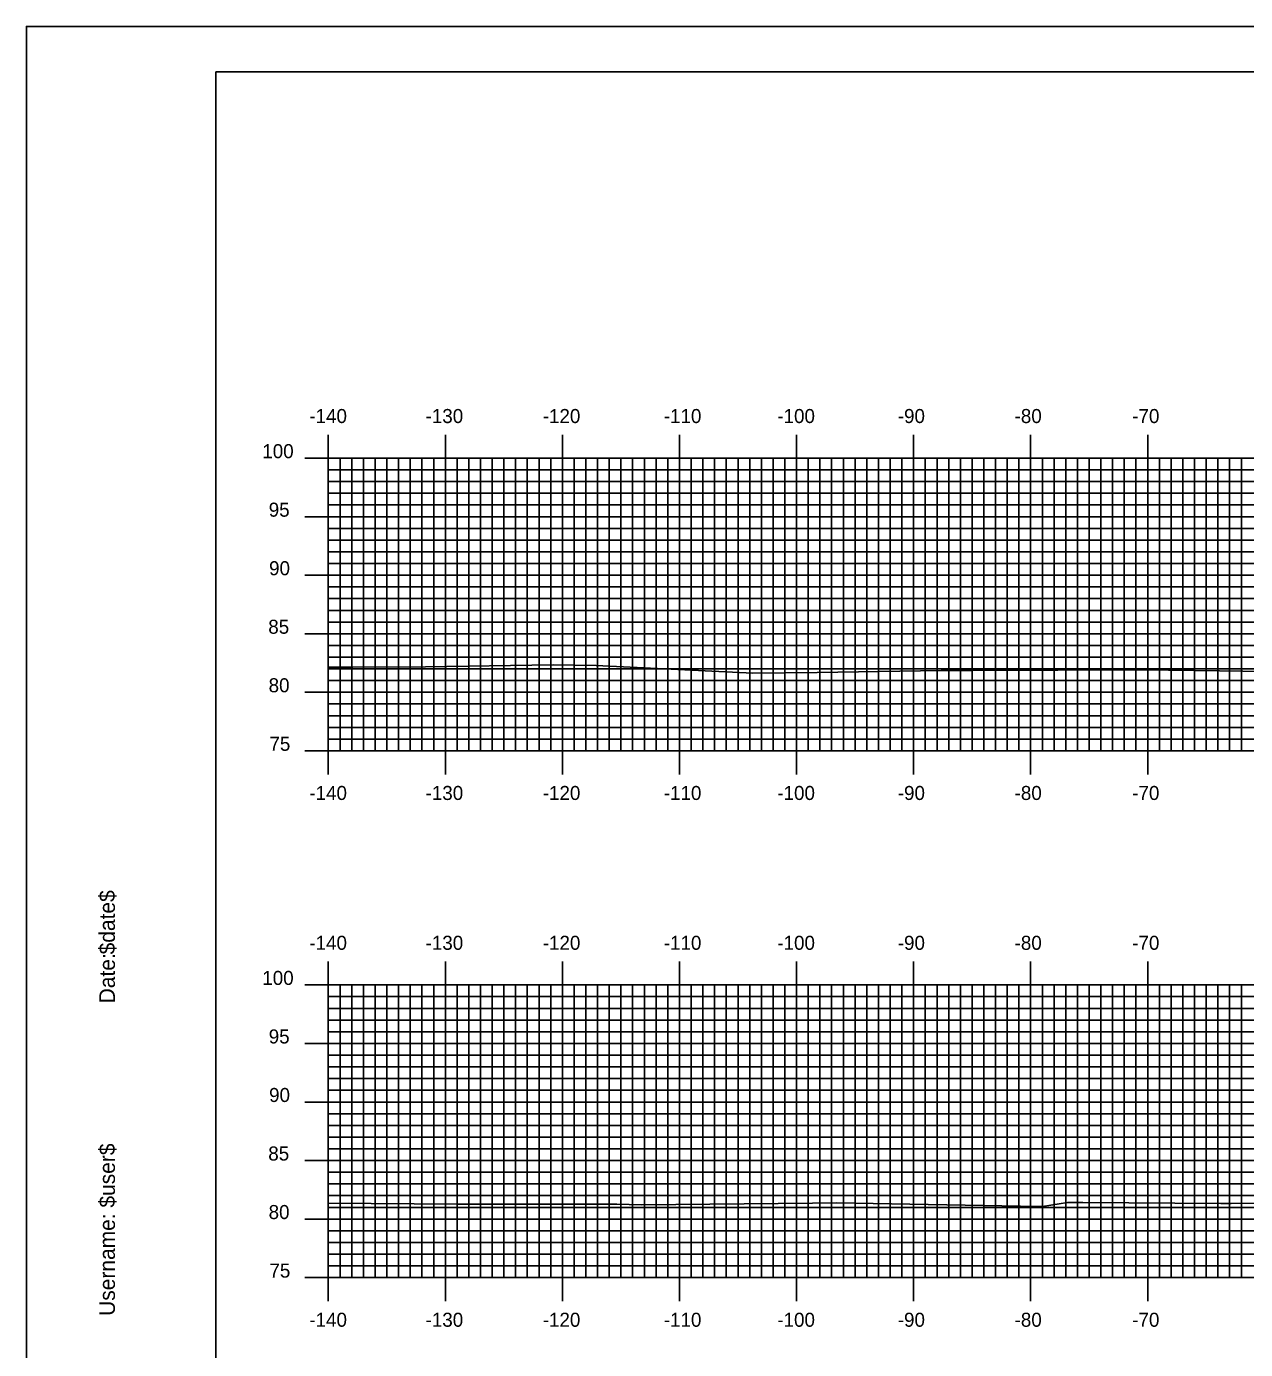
# Model space of a CAD drawing. Extents: x 853723 to 854066, y 364366 to 364586.
# Drawn here: x 853722.9 to 853827.1, y 364472.6 to 364585.7 of the extents above; entities that cross this region are included whole.
import ezdxf

# ---------------------------------------------------------------- set-up
doc = ezdxf.new("R2010")
doc.units = 0
for name, color, linetype in [('BORDER', 7, 'Continuous'), ('H_V ANNOTATION', 7, 'Continuous'), ('MAJOR', 7, 'Continuous'), ('MINOR', 7, 'Continuous'), ('PLOT BOUNDARY', 7, 'Continuous'), ('S_Roadway_Centerline', 7, 'Continuous')]:
    doc.layers.add(name, color=color, linetype=linetype)

msp = doc.modelspace()

# ---------------------------------------------------------------- linework, layer by layer
at = {"layer": 'BORDER'}
msp.add_lwpolyline([(853739.12, 364371.79), (854059.12, 364371.79), (854059.12, 364581.79), (853739.12, 364581.79)], close=True, dxfattribs=at)
at = {"layer": 'MAJOR'}
for p, q in [((853748.72, 364550.79), (853748.72, 364548.79)), ((853758.72, 364550.79), (853758.72, 364548.79)), ((853768.72, 364550.79), (853768.72, 364548.79)), ((853778.72, 364550.79), (853778.72, 364548.79)), ((853788.72, 364550.79), (853788.72, 364548.79)), ((853798.72, 364550.79), (853798.72, 364548.79)), ((853808.72, 364550.79), (853808.72, 364548.79)), ((853818.72, 364550.79), (853818.72, 364548.79)), ((853746.71, 364548.79), (853748.72, 364548.79)), ((853748.72, 364548.79), (854028.72, 364548.79)), ((853748.72, 364523.79), (853748.72, 364548.79)), ((853748.72, 364523.79), (853748.72, 364548.79)), ((853748.72, 364548.79), (854028.72, 364548.79)), ((853758.72, 364523.79), (853758.72, 364548.79)), ((853768.72, 364523.79), (853768.72, 364548.79)), ((853778.72, 364523.79), (853778.72, 364548.79)), ((853788.72, 364523.79), (853788.72, 364548.79)), ((853798.72, 364523.79), (853798.72, 364548.79)), ((853808.72, 364523.79), (853808.72, 364548.79)), ((853818.72, 364523.79), (853818.72, 364548.79)), ((853746.71, 364543.79), (853748.72, 364543.79)), ((853748.72, 364543.79), (854028.72, 364543.79)), ((853746.71, 364538.79), (853748.72, 364538.79)), ((853748.72, 364538.79), (854028.72, 364538.79)), ((853746.71, 364533.79), (853748.72, 364533.79)), ((853748.72, 364533.79), (854028.72, 364533.79)), ((853746.71, 364528.79), (853748.72, 364528.79)), ((853748.72, 364528.79), (854028.72, 364528.79)), ((853746.71, 364523.79), (853748.72, 364523.79)), ((853748.72, 364523.79), (854028.72, 364523.79)), ((853748.72, 364523.79), (854028.72, 364523.79)), ((853748.72, 364521.78), (853748.72, 364523.79)), ((853758.72, 364521.78), (853758.72, 364523.79)), ((853768.72, 364521.78), (853768.72, 364523.79)), ((853778.72, 364521.78), (853778.72, 364523.79)), ((853788.72, 364521.78), (853788.72, 364523.79)), ((853798.72, 364521.78), (853798.72, 364523.79)), ((853808.72, 364521.78), (853808.72, 364523.79)), ((853818.72, 364521.78), (853818.72, 364523.79)), ((853748.72, 364505.79), (853748.72, 364503.79)), ((853758.72, 364505.79), (853758.72, 364503.79)), ((853768.72, 364505.79), (853768.72, 364503.79)), ((853778.72, 364505.79), (853778.72, 364503.79)), ((853788.72, 364505.79), (853788.72, 364503.79)), ((853798.72, 364505.79), (853798.72, 364503.79)), ((853808.72, 364505.79), (853808.72, 364503.79)), ((853818.72, 364505.79), (853818.72, 364503.79)), ((853746.71, 364503.79), (853748.72, 364503.79)), ((853748.72, 364503.79), (854028.72, 364503.79)), ((853748.72, 364478.79), (853748.72, 364503.79)), ((853748.72, 364478.79), (853748.72, 364503.79)), ((853748.72, 364503.79), (854028.72, 364503.79)), ((853758.72, 364478.79), (853758.72, 364503.79)), ((853768.72, 364478.79), (853768.72, 364503.79)), ((853778.72, 364478.79), (853778.72, 364503.79)), ((853788.72, 364478.79), (853788.72, 364503.79)), ((853798.72, 364478.79), (853798.72, 364503.79)), ((853808.72, 364478.79), (853808.72, 364503.79)), ((853818.72, 364478.79), (853818.72, 364503.79)), ((853746.71, 364498.79), (853748.72, 364498.79)), ((853748.72, 364498.79), (854028.72, 364498.79)), ((853746.71, 364493.79), (853748.72, 364493.79)), ((853748.72, 364493.79), (854028.72, 364493.79)), ((853746.71, 364488.79), (853748.72, 364488.79)), ((853748.72, 364488.79), (854028.72, 364488.79)), ((853746.71, 364483.79), (853748.72, 364483.79)), ((853748.72, 364483.79), (854028.72, 364483.79)), ((853746.71, 364478.79), (853748.72, 364478.79)), ((853748.72, 364478.79), (854028.72, 364478.79)), ((853748.72, 364478.79), (854028.72, 364478.79)), ((853748.72, 364476.78), (853748.72, 364478.79)), ((853758.72, 364476.78), (853758.72, 364478.79)), ((853768.72, 364476.78), (853768.72, 364478.79)), ((853778.72, 364476.78), (853778.72, 364478.79)), ((853788.72, 364476.78), (853788.72, 364478.79)), ((853798.72, 364476.78), (853798.72, 364478.79)), ((853808.72, 364476.78), (853808.72, 364478.79)), ((853818.72, 364476.78), (853818.72, 364478.79))]:
    msp.add_line(p, q, dxfattribs=at)
at = {"layer": 'MINOR'}
for p, q in [((853749.72, 364523.79), (853749.72, 364548.79)), ((853750.72, 364523.79), (853750.72, 364548.79)), ((853751.72, 364523.79), (853751.72, 364548.79)), ((853752.72, 364523.79), (853752.72, 364548.79)), ((853753.72, 364523.79), (853753.72, 364548.79)), ((853754.72, 364523.79), (853754.72, 364548.79)), ((853755.72, 364523.79), (853755.72, 364548.79)), ((853756.72, 364523.79), (853756.72, 364548.79)), ((853757.72, 364523.79), (853757.72, 364548.79)), ((853759.72, 364523.79), (853759.72, 364548.79)), ((853760.72, 364523.79), (853760.72, 364548.79)), ((853761.72, 364523.79), (853761.72, 364548.79)), ((853762.72, 364523.79), (853762.72, 364548.79)), ((853763.72, 364523.79), (853763.72, 364548.79)), ((853764.72, 364523.79), (853764.72, 364548.79)), ((853765.72, 364523.79), (853765.72, 364548.79)), ((853766.72, 364523.79), (853766.72, 364548.79)), ((853767.72, 364523.79), (853767.72, 364548.79)), ((853769.72, 364523.79), (853769.72, 364548.79)), ((853770.72, 364523.79), (853770.72, 364548.79)), ((853771.72, 364523.79), (853771.72, 364548.79)), ((853772.72, 364523.79), (853772.72, 364548.79)), ((853773.72, 364523.79), (853773.72, 364548.79)), ((853774.72, 364523.79), (853774.72, 364548.79)), ((853775.72, 364523.79), (853775.72, 364548.79)), ((853776.72, 364523.79), (853776.72, 364548.79)), ((853777.72, 364523.79), (853777.72, 364548.79)), ((853779.72, 364523.79), (853779.72, 364548.79)), ((853780.72, 364523.79), (853780.72, 364548.79)), ((853781.72, 364523.79), (853781.72, 364548.79)), ((853782.72, 364523.79), (853782.72, 364548.79)), ((853783.72, 364523.79), (853783.72, 364548.79)), ((853784.72, 364523.79), (853784.72, 364548.79)), ((853785.72, 364523.79), (853785.72, 364548.79)), ((853786.72, 364523.79), (853786.72, 364548.79)), ((853787.72, 364523.79), (853787.72, 364548.79)), ((853789.72, 364523.79), (853789.72, 364548.79)), ((853790.72, 364523.79), (853790.72, 364548.79)), ((853791.72, 364523.79), (853791.72, 364548.79)), ((853792.72, 364523.79), (853792.72, 364548.79)), ((853793.72, 364523.79), (853793.72, 364548.79)), ((853794.72, 364523.79), (853794.72, 364548.79)), ((853795.72, 364523.79), (853795.72, 364548.79)), ((853796.72, 364523.79), (853796.72, 364548.79)), ((853797.72, 364523.79), (853797.72, 364548.79)), ((853799.72, 364523.79), (853799.72, 364548.79)), ((853800.72, 364523.79), (853800.72, 364548.79)), ((853801.72, 364523.79), (853801.72, 364548.79)), ((853802.72, 364523.79), (853802.72, 364548.79)), ((853803.72, 364523.79), (853803.72, 364548.79)), ((853804.72, 364523.79), (853804.72, 364548.79)), ((853805.72, 364523.79), (853805.72, 364548.79)), ((853806.72, 364523.79), (853806.72, 364548.79)), ((853807.72, 364523.79), (853807.72, 364548.79)), ((853809.72, 364523.79), (853809.72, 364548.79)), ((853810.72, 364523.79), (853810.72, 364548.79)), ((853811.72, 364523.79), (853811.72, 364548.79)), ((853812.72, 364523.79), (853812.72, 364548.79)), ((853813.72, 364523.79), (853813.72, 364548.79)), ((853814.72, 364523.79), (853814.72, 364548.79)), ((853815.72, 364523.79), (853815.72, 364548.79)), ((853816.72, 364523.79), (853816.72, 364548.79)), ((853817.72, 364523.79), (853817.72, 364548.79)), ((853819.72, 364523.79), (853819.72, 364548.79)), ((853820.72, 364523.79), (853820.72, 364548.79)), ((853821.72, 364523.79), (853821.72, 364548.79)), ((853822.72, 364523.79), (853822.72, 364548.79)), ((853823.72, 364523.79), (853823.72, 364548.79)), ((853824.72, 364523.79), (853824.72, 364548.79)), ((853825.72, 364523.79), (853825.72, 364548.79)), ((853826.72, 364523.79), (853826.72, 364548.79)), ((853748.72, 364547.79), (854028.72, 364547.79)), ((853748.72, 364547.79), (853750.72, 364547.79)), ((853748.72, 364546.79), (854028.72, 364546.79)), ((853748.72, 364546.79), (853750.72, 364546.79)), ((853748.72, 364545.79), (854028.72, 364545.79)), ((853748.72, 364545.79), (853750.72, 364545.79)), ((853748.72, 364544.79), (854028.72, 364544.79)), ((853748.72, 364544.79), (853750.72, 364544.79)), ((853748.72, 364542.79), (854028.72, 364542.79)), ((853748.72, 364542.79), (853750.72, 364542.79)), ((853748.72, 364541.79), (854028.72, 364541.79)), ((853748.72, 364541.79), (853750.72, 364541.79)), ((853748.72, 364540.79), (854028.72, 364540.79)), ((853748.72, 364540.79), (853750.72, 364540.79)), ((853748.72, 364539.79), (854028.72, 364539.79)), ((853748.72, 364539.79), (853750.72, 364539.79)), ((853748.72, 364537.79), (854028.72, 364537.79)), ((853748.72, 364537.79), (853750.72, 364537.79)), ((853748.72, 364536.79), (854028.72, 364536.79)), ((853748.72, 364536.79), (853750.72, 364536.79)), ((853748.72, 364535.79), (854028.72, 364535.79)), ((853748.72, 364535.79), (853750.72, 364535.79)), ((853748.72, 364534.79), (854028.72, 364534.79)), ((853748.72, 364534.79), (853750.72, 364534.79)), ((853748.72, 364532.79), (854028.72, 364532.79)), ((853748.72, 364532.79), (853750.72, 364532.79)), ((853748.72, 364531.79), (854028.72, 364531.79)), ((853748.72, 364531.79), (853750.72, 364531.79)), ((853748.72, 364530.79), (854028.72, 364530.79)), ((853748.72, 364530.79), (853750.72, 364530.79)), ((853748.72, 364529.79), (854028.72, 364529.79)), ((853748.72, 364529.79), (853750.72, 364529.79)), ((853748.72, 364527.79), (854028.72, 364527.79)), ((853748.72, 364527.79), (853750.72, 364527.79)), ((853748.72, 364526.79), (854028.72, 364526.79)), ((853748.72, 364526.79), (853750.72, 364526.79)), ((853748.72, 364525.79), (854028.72, 364525.79)), ((853748.72, 364525.79), (853750.72, 364525.79)), ((853748.72, 364524.79), (854028.72, 364524.79)), ((853748.72, 364524.79), (853750.72, 364524.79)), ((853749.72, 364478.79), (853749.72, 364503.79)), ((853750.72, 364478.79), (853750.72, 364503.79)), ((853751.72, 364478.79), (853751.72, 364503.79)), ((853752.72, 364478.79), (853752.72, 364503.79)), ((853753.72, 364478.79), (853753.72, 364503.79)), ((853754.72, 364478.79), (853754.72, 364503.79)), ((853755.72, 364478.79), (853755.72, 364503.79)), ((853756.72, 364478.79), (853756.72, 364503.79)), ((853757.72, 364478.79), (853757.72, 364503.79)), ((853759.72, 364478.79), (853759.72, 364503.79)), ((853760.72, 364478.79), (853760.72, 364503.79)), ((853761.72, 364478.79), (853761.72, 364503.79)), ((853762.72, 364478.79), (853762.72, 364503.79)), ((853763.72, 364478.79), (853763.72, 364503.79)), ((853764.72, 364478.79), (853764.72, 364503.79)), ((853765.72, 364478.79), (853765.72, 364503.79)), ((853766.72, 364478.79), (853766.72, 364503.79)), ((853767.72, 364478.79), (853767.72, 364503.79)), ((853769.72, 364478.79), (853769.72, 364503.79)), ((853770.72, 364478.79), (853770.72, 364503.79)), ((853771.72, 364478.79), (853771.72, 364503.79)), ((853772.72, 364478.79), (853772.72, 364503.79)), ((853773.72, 364478.79), (853773.72, 364503.79)), ((853774.72, 364478.79), (853774.72, 364503.79)), ((853775.72, 364478.79), (853775.72, 364503.79)), ((853776.72, 364478.79), (853776.72, 364503.79)), ((853777.72, 364478.79), (853777.72, 364503.79)), ((853779.72, 364478.79), (853779.72, 364503.79)), ((853780.72, 364478.79), (853780.72, 364503.79)), ((853781.72, 364478.79), (853781.72, 364503.79)), ((853782.72, 364478.79), (853782.72, 364503.79)), ((853783.72, 364478.79), (853783.72, 364503.79)), ((853784.72, 364478.79), (853784.72, 364503.79)), ((853785.72, 364478.79), (853785.72, 364503.79)), ((853786.72, 364478.79), (853786.72, 364503.79)), ((853787.72, 364478.79), (853787.72, 364503.79)), ((853789.72, 364478.79), (853789.72, 364503.79)), ((853790.72, 364478.79), (853790.72, 364503.79)), ((853791.72, 364478.79), (853791.72, 364503.79)), ((853792.72, 364478.79), (853792.72, 364503.79)), ((853793.72, 364478.79), (853793.72, 364503.79)), ((853794.72, 364478.79), (853794.72, 364503.79)), ((853795.72, 364478.79), (853795.72, 364503.79)), ((853796.72, 364478.79), (853796.72, 364503.79)), ((853797.72, 364478.79), (853797.72, 364503.79)), ((853799.72, 364478.79), (853799.72, 364503.79)), ((853800.72, 364478.79), (853800.72, 364503.79)), ((853801.72, 364478.79), (853801.72, 364503.79)), ((853802.72, 364478.79), (853802.72, 364503.79)), ((853803.72, 364478.79), (853803.72, 364503.79)), ((853804.72, 364478.79), (853804.72, 364503.79)), ((853805.72, 364478.79), (853805.72, 364503.79)), ((853806.72, 364478.79), (853806.72, 364503.79)), ((853807.72, 364478.79), (853807.72, 364503.79)), ((853809.72, 364478.79), (853809.72, 364503.79)), ((853810.72, 364478.79), (853810.72, 364503.79)), ((853811.72, 364478.79), (853811.72, 364503.79)), ((853812.72, 364478.79), (853812.72, 364503.79)), ((853813.72, 364478.79), (853813.72, 364503.79)), ((853814.72, 364478.79), (853814.72, 364503.79)), ((853815.72, 364478.79), (853815.72, 364503.79)), ((853816.72, 364478.79), (853816.72, 364503.79)), ((853817.72, 364478.79), (853817.72, 364503.79)), ((853819.72, 364478.79), (853819.72, 364503.79)), ((853820.72, 364478.79), (853820.72, 364503.79)), ((853821.72, 364478.79), (853821.72, 364503.79)), ((853822.72, 364478.79), (853822.72, 364503.79)), ((853823.72, 364478.79), (853823.72, 364503.79)), ((853824.72, 364478.79), (853824.72, 364503.79)), ((853825.72, 364478.79), (853825.72, 364503.79)), ((853826.72, 364478.79), (853826.72, 364503.79)), ((853748.72, 364502.79), (854028.72, 364502.79)), ((853748.72, 364502.79), (853750.72, 364502.79)), ((853748.72, 364501.79), (854028.72, 364501.79)), ((853748.72, 364501.79), (853750.72, 364501.79)), ((853748.72, 364500.79), (854028.72, 364500.79)), ((853748.72, 364500.79), (853750.72, 364500.79)), ((853748.72, 364499.79), (854028.72, 364499.79)), ((853748.72, 364499.79), (853750.72, 364499.79)), ((853748.72, 364497.79), (854028.72, 364497.79)), ((853748.72, 364497.79), (853750.72, 364497.79)), ((853748.72, 364496.79), (854028.72, 364496.79)), ((853748.72, 364496.79), (853750.72, 364496.79)), ((853748.72, 364495.79), (854028.72, 364495.79)), ((853748.72, 364495.79), (853750.72, 364495.79)), ((853748.72, 364494.79), (854028.72, 364494.79)), ((853748.72, 364494.79), (853750.72, 364494.79)), ((853748.72, 364492.79), (854028.72, 364492.79)), ((853748.72, 364492.79), (853750.72, 364492.79)), ((853748.72, 364491.79), (854028.72, 364491.79)), ((853748.72, 364491.79), (853750.72, 364491.79)), ((853748.72, 364490.79), (854028.72, 364490.79)), ((853748.72, 364490.79), (853750.72, 364490.79)), ((853748.72, 364489.79), (854028.72, 364489.79)), ((853748.72, 364489.79), (853750.72, 364489.79)), ((853748.72, 364487.79), (854028.72, 364487.79)), ((853748.72, 364487.79), (853750.72, 364487.79)), ((853748.72, 364486.79), (854028.72, 364486.79)), ((853748.72, 364486.79), (853750.72, 364486.79)), ((853748.72, 364485.79), (854028.72, 364485.79)), ((853748.72, 364485.79), (853750.72, 364485.79)), ((853748.72, 364484.79), (854028.72, 364484.79)), ((853748.72, 364484.79), (853750.72, 364484.79)), ((853748.72, 364482.79), (854028.72, 364482.79)), ((853748.72, 364482.79), (853750.72, 364482.79)), ((853748.72, 364481.79), (854028.72, 364481.79)), ((853748.72, 364481.79), (853750.72, 364481.79)), ((853748.72, 364480.79), (854028.72, 364480.79)), ((853748.72, 364480.79), (853750.72, 364480.79)), ((853748.72, 364479.79), (854028.72, 364479.79)), ((853748.72, 364479.79), (853750.72, 364479.79))]:
    msp.add_line(p, q, dxfattribs=at)
at = {"layer": 'PLOT BOUNDARY'}
msp.add_lwpolyline([(853722.93, 364365.67), (854062.93, 364365.67), (854062.93, 364585.67), (853722.93, 364585.67)], close=True, dxfattribs=at)
at = {"layer": 'S_Roadway_Centerline'}
for points in [[(853748.72, 364530.94), (853750.82, 364530.95), (853757.02, 364530.96), (853767.92, 364531.13), (853771.61, 364531.07), (853785, 364530.42), (853790.47, 364530.48), (853801.08, 364530.66), (853803.74, 364530.64), (853818.32, 364530.72), (853824.84, 364530.62), (853834.76, 364530.49), (853844.74, 364530.59), (853851.56, 364530.54), (853856.41, 364530.64), (853868.67, 364530.88), (853880.78, 364530.66), (853885.5, 364530.58), (853886.66, 364530.58), (853901.73, 364530.89), (853906.72, 364530.81), (853918.61, 364530.5), (853926.17, 364530.58), (853935.19, 364530.75)], [(853748.72, 364485.14), (853759.74, 364485.06), (853773.37, 364485.07), (853775.47, 364485.02), (853790.09, 364485.14), (853792.1, 364485.19), (853809.41, 364484.87), (853809.74, 364484.86), (853811.87, 364485.2), (853813.17, 364485.2), (853824.98, 364485.12), (853825.86, 364485.13), (853842.1, 364485.15)]]:
    msp.add_lwpolyline(points, dxfattribs=at)

# ---------------------------------------------------------------- texts
at = {"layer": 'BORDER'}
for s, p in [('$date$', (853730.49, 364506.4)), ('Date:', (853730.49, 364502.22)), ('$user$', (853730.49, 364484.77)), ('Username:', (853730.49, 364475.52))]:
    msp.add_text(s, height=1.339, rotation=90, dxfattribs=at).set_placement(p)
at = {"layer": 'H_V ANNOTATION'}
for s, p in [('-140', (853747.1, 364551.79)), ('-130', (853757.03, 364551.79)), ('-120', (853767.04, 364551.79)), ('-110', (853777.38, 364551.79)), ('-100', (853787.08, 364551.79)), ('-90', (853797.37, 364551.79)), ('-80', (853807.35, 364551.79)), ('-70', (853817.4, 364551.79)), ('100', (853743.08, 364548.79)), ('95', (853743.63, 364543.79)), ('90', (853743.66, 364538.79)), ('85', (853743.59, 364533.79)), ('80', (853743.62, 364528.79)), ('75', (853743.69, 364523.79)), ('-140', (853747.1, 364519.59)), ('-130', (853757.03, 364519.59)), ('-120', (853767.04, 364519.59)), ('-110', (853777.38, 364519.59)), ('-100', (853787.08, 364519.59)), ('-90', (853797.37, 364519.59)), ('-80', (853807.35, 364519.59)), ('-70', (853817.4, 364519.59)), ('-140', (853747.1, 364506.79)), ('-130', (853757.03, 364506.79)), ('-120', (853767.04, 364506.79)), ('-110', (853777.38, 364506.79)), ('-100', (853787.08, 364506.79)), ('-90', (853797.37, 364506.79)), ('-80', (853807.35, 364506.79)), ('-70', (853817.4, 364506.79)), ('100', (853743.08, 364503.79)), ('95', (853743.63, 364498.79)), ('90', (853743.66, 364493.79)), ('85', (853743.59, 364488.79)), ('80', (853743.62, 364483.79)), ('75', (853743.69, 364478.79)), ('-140', (853747.1, 364474.59)), ('-130', (853757.03, 364474.59)), ('-120', (853767.04, 364474.59)), ('-110', (853777.38, 364474.59)), ('-100', (853787.08, 364474.59)), ('-90', (853797.37, 364474.59)), ('-80', (853807.35, 364474.59)), ('-70', (853817.4, 364474.59))]:
    msp.add_text(s, height=1.2, dxfattribs=at).set_placement(p)
at = {"layer": 'MAJOR'}
for p in [(853748.71, 364523.79), (853748.71, 364478.79)]:
    msp.add_text('-', height=0.012, dxfattribs=at).set_placement(p)

doc.saveas('drawing.dxf')
